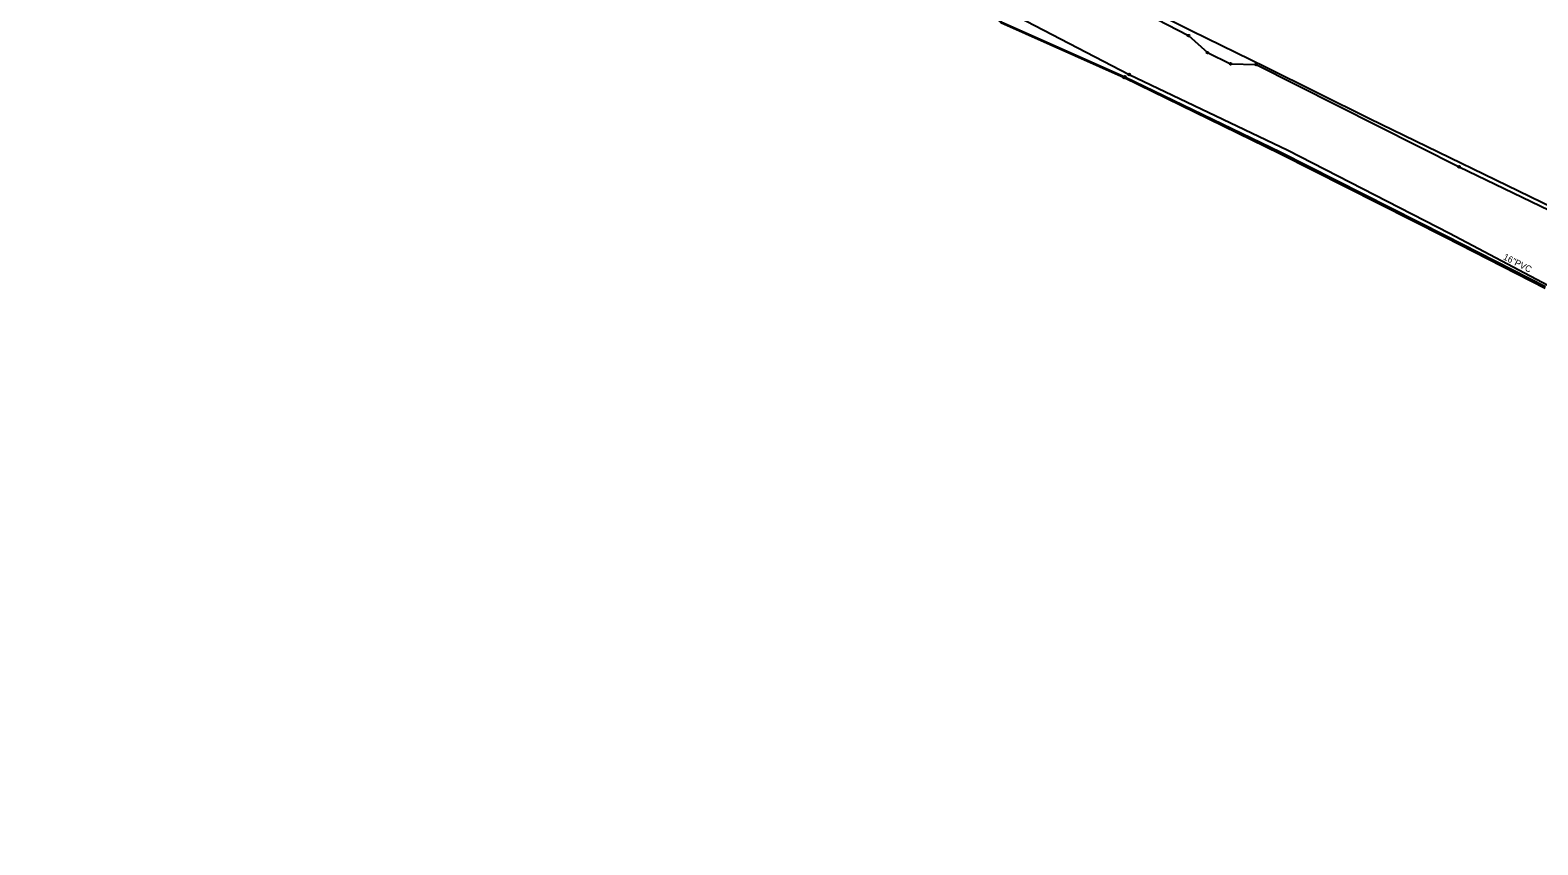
# Model space of a CAD drawing. Extents: x 2244485 to 2250986, y 199568 to 203007.
# Drawn here: x 2249364 to 2250182, y 199603 to 200045 of the extents above; entities that cross this region are included whole.
import ezdxf

# ---------------------------------------------------------------- set-up
doc = ezdxf.new("R2010")
doc.units = 0
for name, color, linetype in [('Default', 7, 'Continuous'), ('Exist Utilities Telephone UG FO SUE LOS B', 7, 'Continuous'), ('Exist Utilities Telephone UG FO SUE LOS C', 7, 'Continuous'), ('Exist Utilities Water UG Line SUE LOS B', 7, 'Continuous'), ('Exist Utilities Water UG Line SUE LOS B Text', 7, 'Continuous')]:
    doc.layers.add(name, color=color, linetype=linetype)

# ---------------------------------------------------------------- blocks, each defined once
blk = doc.blocks.new('SurveyPointCell')
at = {"layer": 'Default'}
for p, q in [((-0.5, 0), (0.5, 0)), ((0, -0.5), (0, 0.5))]:
    blk.add_line(p, q, dxfattribs=at)
blk.add_circle((0, 0), 0.5, dxfattribs=at)

msp = doc.modelspace()

# ---------------------------------------------------------------- linework, layer by layer
at = {"layer": 'Exist Utilities Telephone UG FO SUE LOS B'}
for points in [[(2249319.08, 200376.82), (2249375.45, 200350.06), (2249435.96, 200321), (2249525.24, 200277.08), (2249685.23, 200197.6), (2249751.73, 200164.33), (2249867.18, 200107.28), (2249992.37, 200042.44), (2250002.65, 200033.19), (2250015.25, 200027.15), (2250029.09, 200026.7), (2250139.17, 199971.22), (2250192.89, 199945.32), (2250247.36, 199918.05), (2250358.97, 199862.45), (2250517.75, 199783.98), (2250572.3, 199756.11), (2250629.61, 199728.08), (2250729.22, 199678.8), (2250785.25, 199651.26), (2250842.24, 199622.75), (2250880.78, 199603.41)], [(2249313.69, 200339.47), (2249478.6, 200256.38), (2249537.07, 200228.67), (2249598.27, 200197.54), (2249663.63, 200164.83), (2249773.21, 200111.95), (2249861.46, 200067.53), (2249880.8, 200058.34), (2249887.69, 200054.78), (2249888.29, 200051.61), (2249890.49, 200049.61), (2249957.47, 200019.71), (2250041.91, 199978.42), (2250131.82, 199933.16), (2250185.86, 199905.35)], [(2249314.07, 200340.07), (2249478.96, 200257.14), (2249537.25, 200229.25), (2249598.66, 200198.18), (2249664.06, 200165.51), (2249773.44, 200112.37), (2249861.61, 200068.16), (2249881.32, 200059.05), (2249888.07, 200054.88), (2249888.39, 200051.59), (2249888.39, 200051.59), (2249890.69, 200049.91), (2249957.88, 200020.15), (2250042.43, 199979.26), (2250131.9, 199933.91), (2250186.19, 199906.28)]]:
    msp.add_lwpolyline(points, dxfattribs=at)
at = {"layer": 'Exist Utilities Telephone UG FO SUE LOS C'}
msp.add_lwpolyline([(2249352.73, 200362.96), (2249442.05, 200319.48), (2249492.68, 200294.13), (2249525.95, 200279.04), (2249648.71, 200218.15), (2249719.19, 200182.58), (2249840.2, 200122.41), (2249994.21, 200045.08), (2250034.19, 200025.56), (2250090.65, 199997.4), (2250196.48, 199946.19), (2250343.78, 199872.69), (2250476.54, 199806.8), (2250567.69, 199761.35), (2250630.72, 199730.05), (2250730.23, 199680.67), (2250881.91, 199605.67)], dxfattribs=at)
at = {"layer": 'Exist Utilities Water UG Line SUE LOS B'}
msp.add_lwpolyline([(2249895.12, 200055.15), (2249960.22, 200021.32), (2250046.31, 199980.22), (2250134.08, 199935.34), (2250187.34, 199906.97), (2250250.6, 199876.16), (2250380.36, 199808.54), (2250547.37, 199734.1), (2250673.91, 199668.64), (2250777.46, 199619.82)], dxfattribs=at)

# ---------------------------------------------------------------- block references
at = {"layer": 'Default'}
for p in [(2249992.37, 200042.44), (2250002.65, 200033.19), (2249960.22, 200021.32), (2250015.25, 200027.15), (2250029.09, 200026.7), (2249957.47, 200019.71), (2249957.88, 200020.15), (2250139.17, 199971.22)]:
    msp.add_blockref('SurveyPointCell', p, dxfattribs=at)

# ---------------------------------------------------------------- texts
at = {"layer": 'Exist Utilities Water UG Line SUE LOS B Text'}
msp.add_text('16"PVC', height=3.5, rotation=333.09153, dxfattribs=at).set_placement((2250162.81, 199921.23))

doc.saveas('drawing.dxf')
